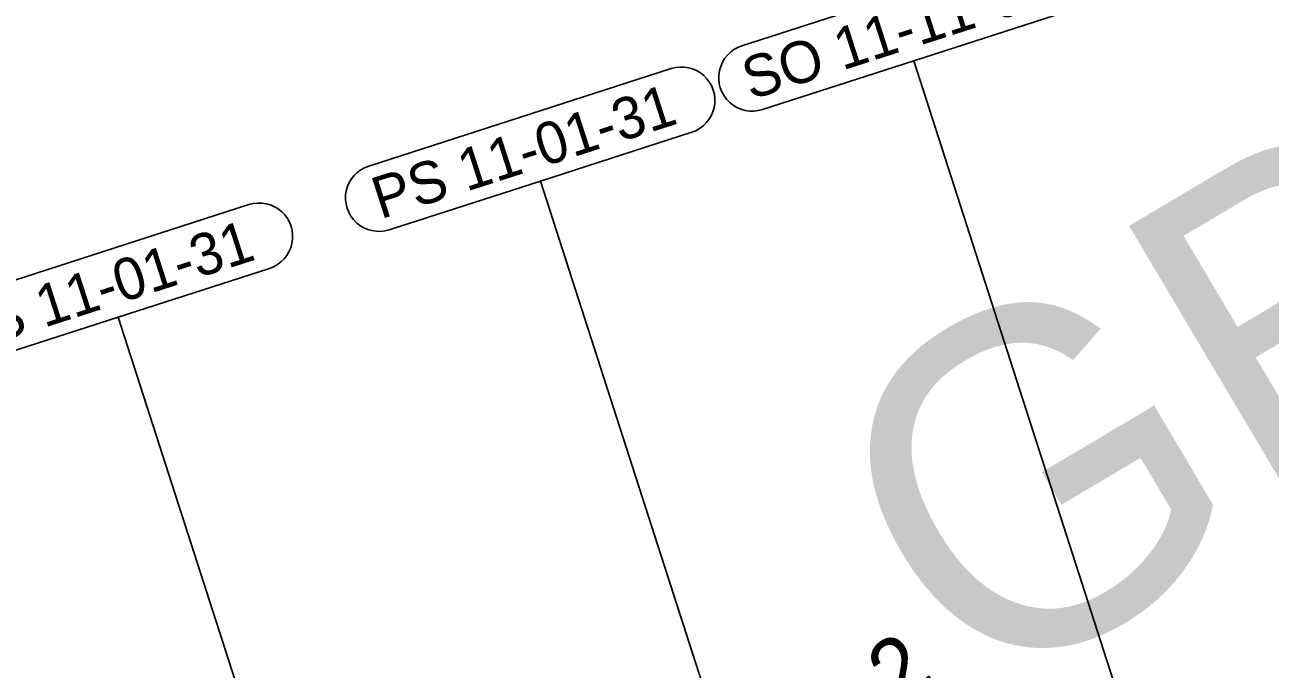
# Model space of a CAD drawing. Extents: x -759005 to -757278, y -1175311 to -1173953.
# Drawn here: x -758451.1 to -758376.7, y -1174802.3 to -1174763.8 of the extents above; entities that cross this region are included whole.
import ezdxf

# ---------------------------------------------------------------- set-up
doc = ezdxf.new("R2010")
doc.units = 0
for name, color, linetype in [('_NOR-návrh tenká', 7, 'Continuous'), ('_NOR-osa', 7, 'Continuous'), ('_NOR-popis', 7, 'Continuous'), ('Vrstva 53', 7, 'Continuous'), ('Vrstva 7', 7, 'Continuous')]:
    doc.layers.add(name, color=color, linetype=linetype)

msp = doc.modelspace()

# ---------------------------------------------------------------- linework, layer by layer
at = {"layer": '_NOR-návrh tenká'}
for radius, start, end in [(295.6, 97.09776, 129.28488), (294.75, 97.0979, 129.28474), (291.3, 97.09848, 129.28417), (290.55, 97.09861, 129.28404)]:
    msp.add_arc((-758205.34, -1175057.864), radius, start, end, dxfattribs=at)
at = {"layer": '_NOR-osa'}
msp.add_arc((-758205.34, -1175057.864), 293, 97.09819, 129.28445, dxfattribs=at)
at = {"layer": '_NOR-popis'}
for points in [[(-758408.266, -1174765.01), (-758390.181, -1174759.184)], [(-758388.955, -1174762.992), (-758397.997, -1174765.904), (-758378.816, -1174825.453)], [(-758430.578, -1174772.196), (-758412.493, -1174766.371)], [(-758397.997, -1174765.904), (-758407.04, -1174768.817)], [(-758411.267, -1174770.178), (-758420.309, -1174773.091), (-758401.541, -1174831.358)], [(-758420.309, -1174773.091), (-758429.352, -1174776.004)], [(-758455.818, -1174780.326), (-758437.733, -1174774.501)], [(-758436.507, -1174778.308), (-758445.549, -1174781.221), (-758425.724, -1174842.771)], [(-758445.549, -1174781.221), (-758454.592, -1174784.134)]]:
    msp.add_lwpolyline(points, dxfattribs=at)
for centre, start, end in [((-758407.653, -1174766.913), 107.85402, 287.85473), ((-758411.88, -1174768.275), 287.85331, 107.85402), ((-758429.965, -1174774.1), 107.85402, 287.85473), ((-758437.12, -1174776.405), 287.85331, 107.85402)]:
    msp.add_arc(centre, 2, start, end, dxfattribs=at)

# ---------------------------------------------------------------- texts
for s, p in [('SO 11-11-01', (-758407.742, -1174768.255)), ('PS 11-01-31', (-758429.87, -1174775.383)), ('PS 11-01-31', (-758455.11, -1174783.513))]:
    msp.add_text(s, height=2.5, rotation=17.85402, dxfattribs=at).set_placement(p)
at = {"layer": 'Vrstva 53'}
msp.add_text('GB1015', height=20, rotation=30.69125, dxfattribs=at).set_placement((-758394.685, -1174804.707))
at = {"layer": 'Vrstva 7'}
msp.add_text('106,2', height=3.75, rotation=38.19355, dxfattribs=at).set_placement((-758406.498, -1174810.546))

doc.saveas('drawing.dxf')
